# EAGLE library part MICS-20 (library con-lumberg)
CONNECTOR
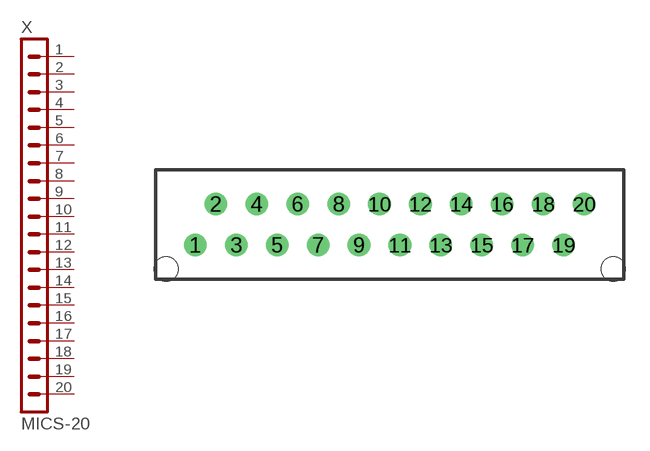
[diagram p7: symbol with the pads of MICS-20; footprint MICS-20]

Designator prefix X

## MICS-20 (MPN: MICS 20; OC_FARNELL: 1216998; OC_NEWARK: 97K5081)  [MICS-20]
1  1  pas
2  2  pas
3  3  pas
4  4  pas
5  5  pas
6  6  pas
7  7  pas
8  8  pas
9  9  pas
10  10  pas
11  11  pas
12  12  pas
13  13  pas
14  14  pas
15  15  pas
16  16  pas
17  17  pas
18  18  pas
19  19  pas
20  20  pas

## Footprint MICS-20 (pad centres in mm)
CONNECTOR
drill 0.85 pad 1.397 round: 1 -12.065,-1.27; 2 -10.795,1.27; 3 -9.525,-1.27; 4 -8.255,1.27; 5 -6.985,-1.27; 6 -5.715,1.27; 7 -4.445,-1.27; 8 -3.175,1.27; 9 -1.905,-1.27; 10 -0.635,1.27; 11 0.635,-1.27; 12 1.905,1.27; 13 3.175,-1.27; 14 4.445,1.27; 15 5.715,-1.27; 16 6.985,1.27; 17 8.255,-1.27; 18 9.525,1.27; 19 10.795,-1.27; 20 12.065,1.27
hole 1.5 at 13.865,-2.75
hole 1.5 at -13.865,-2.75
